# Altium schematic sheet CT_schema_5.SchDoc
size 255 x 245 mm
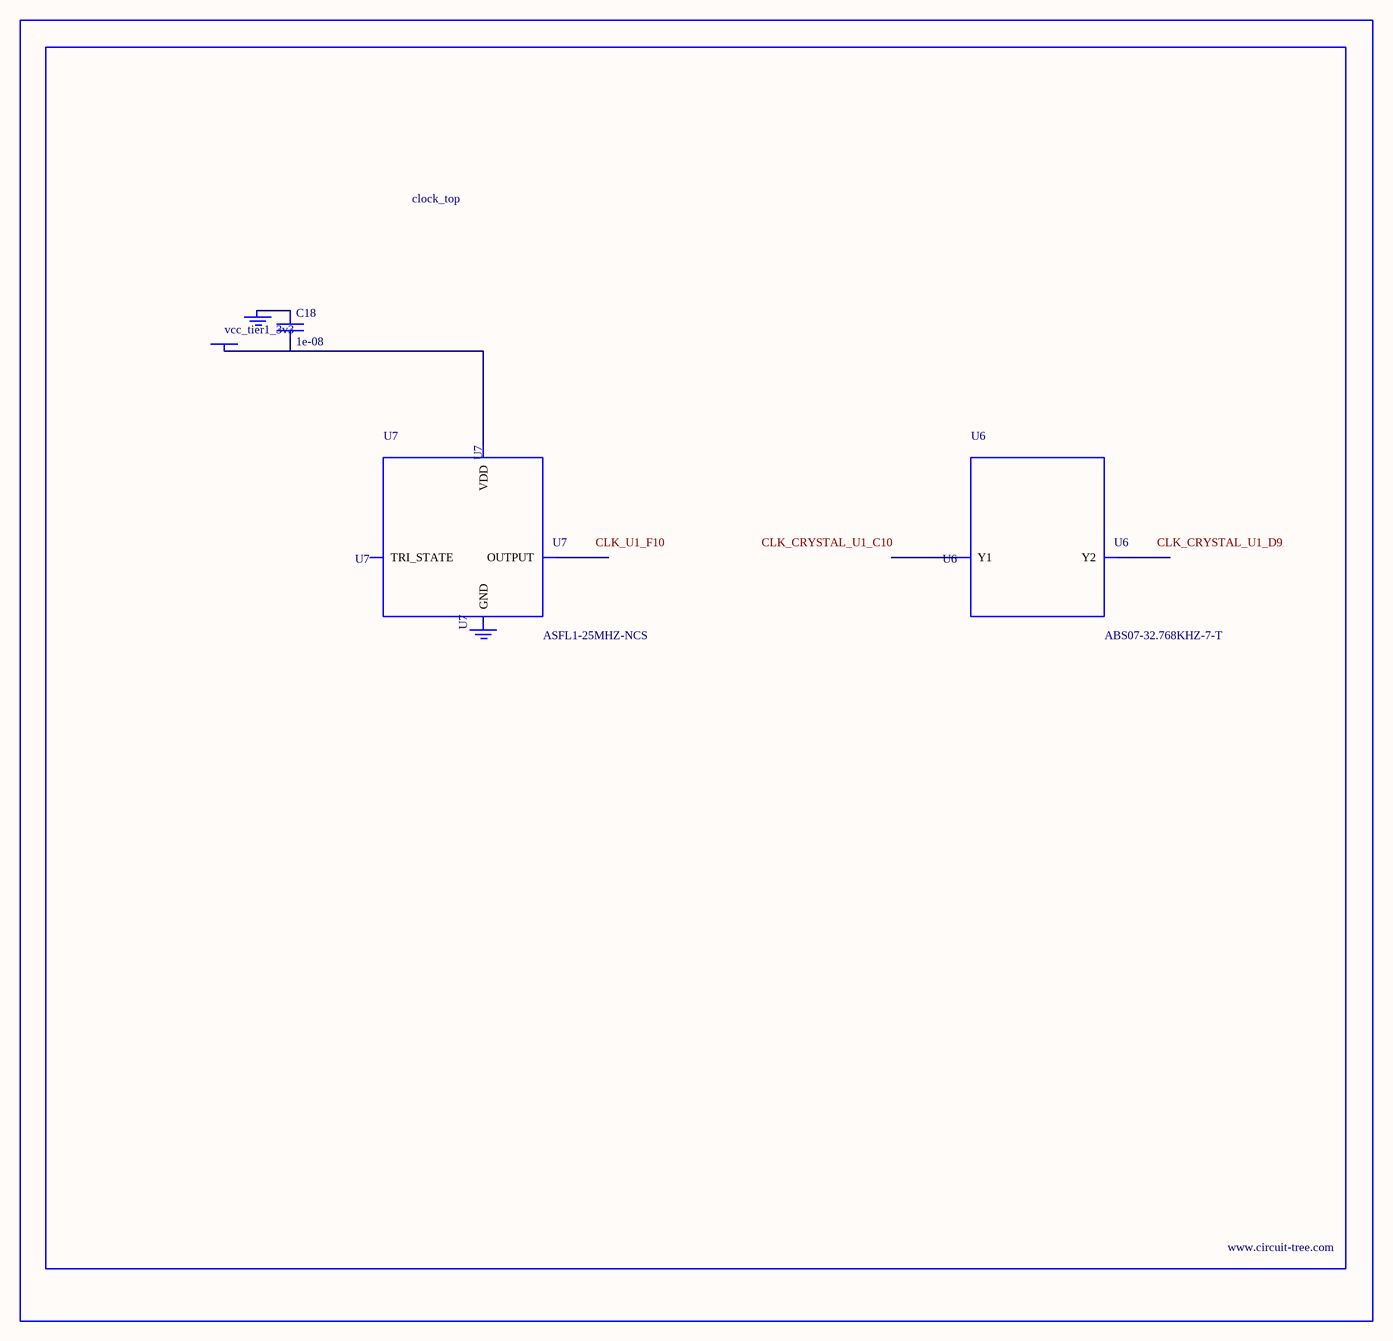
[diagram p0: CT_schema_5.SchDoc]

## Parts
BORDER4  (no value)
C18  1e-08  [C0402]
GND_INSTANCE_4_0  (no value)
GND_INSTANCE_4_1  (no value)
POWER_INSTANCE_4_0  vcc_tier1_3v3
U6  ABS07-32.768KHZ-7-T  [ABS07-32.768KHZ-7-T]
U7  ASFL1-25MHZ-NCS  [ASFL1]

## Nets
NetC18_1: C18.1 GND_INSTANCE_4_0.0(GND)
NetC18_2: C18.2 POWER_INSTANCE_4_0.0(PWR) U7.4(VDD)

Not connected (* = marked no-connect by the designer): GND_INSTANCE_4_1 0(GND); U6 1(Y1) 2(Y2); U7 1(TRI_STATE) 2(GND) 3(OUTPUT)

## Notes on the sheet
- Labels drawn without touching a wire or pin: CLK_CRYSTAL_U1_C10, CLK_CRYSTAL_U1_D9, CLK_U1_F10

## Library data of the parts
BORDER4 = BORDER_PAGE4
C18 = C0402C103K3RAC
GND_INSTANCE_4_0 GND_INSTANCE_4_1 = GND
POWER_INSTANCE_4_0 = PWR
